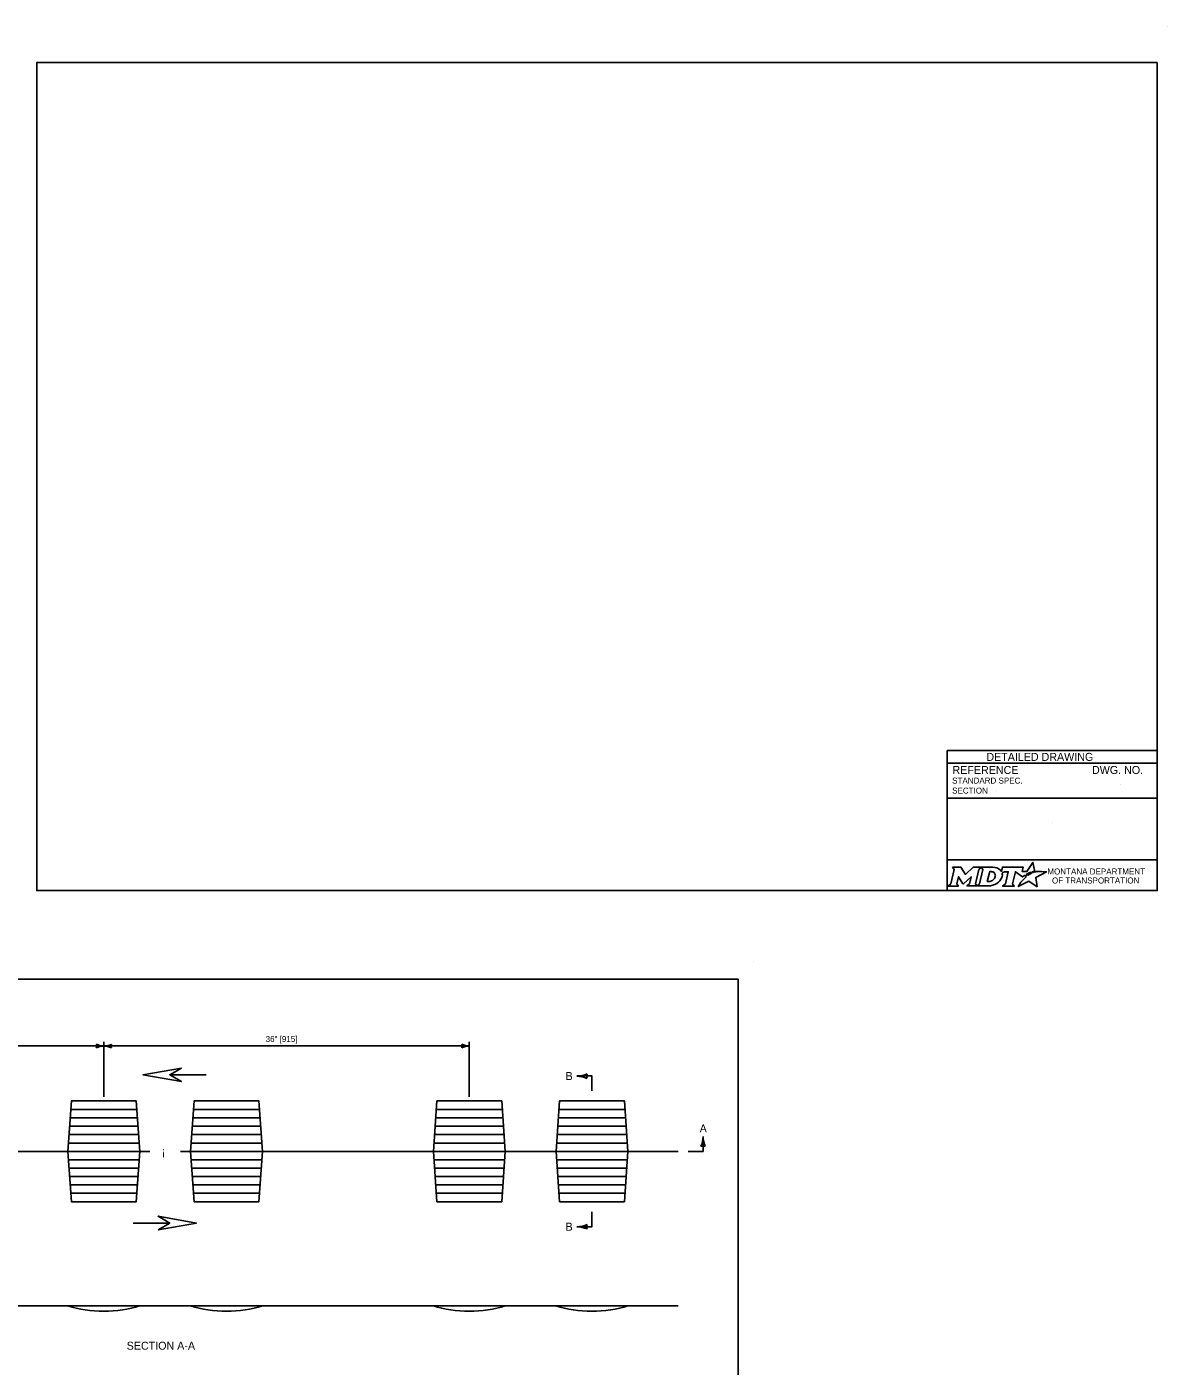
# Model space of a CAD drawing. Extents: x 49937 to 50080, y 49883 to 50108.
# Drawn here: x 50009.64 to 50021.04, y 49995.13 to 50008.52 of the extents above; entities that cross this region are included whole.
import ezdxf

# ---------------------------------------------------------------- set-up
doc = ezdxf.new("R2010")
doc.units = 0
for name, color, linetype in [('Default', 7, 'Continuous'), ('Level 1', 7, 'Continuous'), ('Level 2', 7, 'Continuous'), ('Level 3', 7, 'Continuous'), ('Level 4', 7, 'Continuous'), ('Level 5', 7, 'Continuous'), ('Level 6', 7, 'Continuous')]:
    doc.layers.add(name, color=color, linetype=linetype)

msp = doc.modelspace()

# ---------------------------------------------------------------- linework, layer by layer
at = {"layer": 'Default'}
for points in [[(50018.893, 50000.121), (50018.907, 50000.097), (50018.874, 49999.954), (50018.848, 49999.931), (50018.95, 49999.931), (50018.936, 49999.954), (50018.952, 50000.024), (50018.996, 49999.955), (50019.002, 49999.955), (50019.077, 50000.025), (50019.06, 49999.954), (50019.035, 49999.932), (50019.137, 49999.932), (50019.123, 49999.955), (50019.156, 50000.097)], [(50019.156, 50000.097), (50019.182, 50000.121), (50019.099, 50000.121), (50019.02, 50000.048), (50018.975, 50000.12), (50018.893, 50000.121)], [(50019.295, 50000.121), (50019.182, 50000.121), (50019.196, 50000.098), (50019.163, 49999.954), (50019.137, 49999.932), (50019.248, 49999.932)], [(50019.7, 50000.068), (50019.69, 50000.074), (50019.702, 50000.076), (50019.713, 50000.078), (50019.696, 50000.168), (50019.636, 50000.077), (50019.589, 50000.076), (50019.599, 50000.12), (50019.39, 50000.121), (50019.38, 50000.078), (50019.374, 50000.086)], [(50019.319, 50000.034), (50019.318, 50000.026), (50019.315, 50000.017), (50019.311, 50000.008), (50019.305, 50000.001), (50019.299, 49999.994), (50019.291, 49999.988), (50019.282, 49999.983), (50019.273, 49999.979), (50019.264, 49999.977), (50019.255, 49999.976), (50019.239, 49999.976), (50019.263, 50000.076), (50019.279, 50000.076), (50019.286, 50000.075), (50019.294, 50000.073), (50019.301, 50000.07), (50019.307, 50000.066), (50019.311, 50000.061), (50019.315, 50000.055), (50019.318, 50000.049), (50019.319, 50000.042), (50019.32, 50000.038), (50019.319, 50000.034)], [(50019.293, 49999.939), (50019.302, 49999.942), (50019.315, 49999.947), (50019.335, 49999.958)], [(50019.387, 50000.062), (50019.411, 50000.075), (50019.448, 50000.075), (50019.42, 49999.954), (50019.392, 49999.931), (50019.508, 49999.931), (50019.491, 49999.954), (50019.52, 50000.075), (50019.591, 50000.023), (50019.612, 50000.038), (50019.632, 50000.027)], [(50019.576, 49999.971), (50019.561, 49999.947), (50019.556, 49999.939), (50019.55, 49999.931), (50019.548, 49999.926), (50019.653, 49999.979), (50019.737, 49999.924), (50019.724, 50000.017), (50019.831, 50000.075), (50019.782, 50000.076), (50019.751, 50000.077), (50019.731, 50000.077), (50019.724, 50000.075), (50019.719, 50000.074), (50019.711, 50000.072), (50019.7, 50000.068)], [(50019.59, 49999.987), (50019.59, 49999.987)], [(50019.65, 50000.04), (50019.648, 50000.039), (50019.629, 50000.048), (50019.639, 50000.054), (50019.644, 50000.056), (50019.652, 50000.06), (50019.658, 50000.063), (50019.666, 50000.066), (50019.673, 50000.068), (50019.685, 50000.061), (50019.681, 50000.059), (50019.676, 50000.056), (50019.672, 50000.054), (50019.667, 50000.051), (50019.665, 50000.05), (50019.662, 50000.049), (50019.66, 50000.047), (50019.658, 50000.046), (50019.655, 50000.044), (50019.652, 50000.042), (50019.65, 50000.04)]]:
    msp.add_lwpolyline(points, dxfattribs=at)
for centre, radius, start, end in [((50019.274, 50000.059), 0.118, 300.9103, 339.1383), ((50019.319, 50000.042), 0.0709, 339.5329, 15.8582)]:
    msp.add_arc(centre, radius, start, end, dxfattribs=at)
for centre, major_axis, ratio, start_param, end_param in [((50019.293, 50000.073), (0.0834, -0.0037), 0.568097, 0.61298, 1.570796), ((50019.349, 50000.081), (0.0361, -0.0295), 0.469099, 1.225588, 1.570796), ((50019.583, 49999.979), (-0.00694, -0.00806), 0.008222, 0, 3.137361), ((50019.6, 49999.997), (-0.0098, -0.0102), 0.016458, 3.141593, 6.279097), ((50019.621, 50000.017), (-0.0112, -0.0097), 0.021651, 3.157348, 6.283185), ((50019.248, 50000.08), (0, 0.148), 0.987302, 3.139398, 3.456847)]:
    msp.add_ellipse(centre, major_axis=major_axis, ratio=ratio, start_param=start_param, end_param=end_param, dxfattribs=at)
at = {"layer": 'Level 1'}
for p, q in [((50021.038, 50008.524), (50021.038, 50008.524)), ((50016.9, 49999.176), (50016.9, 49999.176)), ((50011.432, 49998.044), (50011.066, 49998.044)), ((50011.432, 49998.043), (50011.066, 49998.043)), ((50010.077, 49997.698), (50010.737, 49997.698)), ((50011.303, 49997.698), (50011.964, 49997.698)), ((50013.731, 49997.698), (50014.391, 49997.698)), ((50014.957, 49997.698), (50015.617, 49997.698)), ((50010.071, 49997.614), (50010.743, 49997.614)), ((50011.298, 49997.614), (50011.969, 49997.614)), ((50013.725, 49997.614), (50014.397, 49997.614)), ((50014.951, 49997.614), (50015.623, 49997.614)), ((50010.06, 49997.446), (50010.755, 49997.446)), ((50010.065, 49997.53), (50010.749, 49997.53)), ((50011.286, 49997.446), (50011.981, 49997.446)), ((50011.292, 49997.53), (50011.975, 49997.53)), ((50013.713, 49997.446), (50014.409, 49997.446)), ((50013.719, 49997.53), (50014.403, 49997.53)), ((50014.94, 49997.446), (50015.635, 49997.446)), ((50014.946, 49997.53), (50015.629, 49997.53)), ((50010.054, 49997.362), (50010.761, 49997.362)), ((50011.28, 49997.362), (50011.987, 49997.362)), ((50013.708, 49997.362), (50014.415, 49997.362)), ((50014.934, 49997.362), (50015.641, 49997.362)), ((50010.054, 49997.194), (50010.761, 49997.194)), ((50011.28, 49997.194), (50011.987, 49997.194)), ((50013.708, 49997.194), (50014.415, 49997.194)), ((50014.934, 49997.194), (50015.641, 49997.194)), ((50010.06, 49997.11), (50010.755, 49997.11)), ((50010.065, 49997.026), (50010.749, 49997.026)), ((50011.286, 49997.11), (50011.981, 49997.11)), ((50011.292, 49997.026), (50011.975, 49997.026)), ((50013.713, 49997.11), (50014.409, 49997.11)), ((50013.719, 49997.026), (50014.403, 49997.026)), ((50014.94, 49997.11), (50015.635, 49997.11)), ((50014.946, 49997.026), (50015.629, 49997.026)), ((50010.071, 49996.943), (50010.743, 49996.943)), ((50011.298, 49996.943), (50011.969, 49996.943)), ((50013.725, 49996.943), (50014.397, 49996.943)), ((50014.951, 49996.943), (50015.623, 49996.943)), ((50010.077, 49996.859), (50010.737, 49996.859)), ((50011.303, 49996.859), (50011.964, 49996.859)), ((50013.731, 49996.859), (50014.391, 49996.859)), ((50014.957, 49996.859), (50015.617, 49996.859)), ((50010.702, 49996.561), (50011.067, 49996.561)), ((50010.702, 49996.561), (50011.067, 49996.561)), ((50005.894, 49995.734), (50016.148, 49995.734))]:
    msp.add_line(p, q, dxfattribs=at)
for points in [[(50020.938, 50008.165), (50009.737, 50008.165), (50009.737, 49999.886), (50020.938, 49999.886)], [(49999.384, 49998.999), (50016.75, 49998.999), (50016.75, 49987.799), (49999.384, 49987.799)], [(50011.183, 49998.111), (50010.799, 49998.044), (50011.183, 49997.976), (50011.066, 49998.044)], [(50010.048, 49997.278), (50010.083, 49997.782), (50010.732, 49997.782), (50010.767, 49997.278), (50010.732, 49996.775), (50010.083, 49996.775)], [(50011.274, 49997.278), (50011.309, 49997.782), (50011.958, 49997.782), (50011.993, 49997.278), (50011.958, 49996.775), (50011.309, 49996.775)], [(50013.702, 49997.278), (50013.737, 49997.782), (50014.385, 49997.782), (50014.42, 49997.278), (50014.385, 49996.775), (50013.737, 49996.775)], [(50014.928, 49997.278), (50014.963, 49997.782), (50015.612, 49997.782), (50015.647, 49997.278), (50015.612, 49996.775), (50014.963, 49996.775)], [(50010.95, 49996.493), (50011.333, 49996.561), (50010.95, 49996.629), (50011.067, 49996.561)]]:
    msp.add_lwpolyline(points, close=True, dxfattribs=at)
for centre in [(50010.407, 49996.013), (50011.634, 49996.013), (50014.061, 49996.013), (50015.287, 49996.013)]:
    msp.add_ellipse(centre, major_axis=(0.655, 0), ratio=0.509728, start_param=4.131771, end_param=5.293007, dxfattribs=at)
at = {"layer": 'Level 3'}
for p, q in [((50010.407, 49997.822), (50010.407, 49998.372)), ((50014.061, 49997.822), (50014.061, 49998.372)), ((50007.98, 49998.332), (50010.407, 49998.332)), ((50010.407, 49998.332), (50014.061, 49998.332))]:
    msp.add_line(p, q, dxfattribs=at)
for centre, radius, start, end in [((50010.416, 49998.554), 0.222, 247.4703, 267.6538), ((50010.279, 49998.331), 0.0548, 342.1531, 17.8755), ((50010.396, 49998.564), 0.233, 272.8416, 292.0915), ((50010.535, 49998.332), 0.0548, 162.1531, 197.8755), ((50014.07, 49998.554), 0.222, 247.4703, 267.6538), ((50013.933, 49998.331), 0.0548, 342.1531, 17.8755), ((50010.419, 49998.099), 0.233, 92.8416, 112.0915), ((50010.398, 49998.109), 0.222, 67.4703, 87.6538), ((50014.073, 49998.099), 0.233, 92.8416, 112.0915)]:
    msp.add_arc(centre, radius, start, end, dxfattribs=at)
at = {"layer": 'Level 4'}
for p, q in [((50020.938, 50001.286), (50018.838, 50001.286)), ((50018.838, 50001.286), (50018.838, 49999.886)), ((50020.938, 50001.161), (50018.838, 50001.161)), ((50020.574, 50000.946), (50020.574, 50000.946)), ((50020.938, 50000.811), (50018.838, 50000.811)), ((50019.332, 50000.886), (50019.332, 50000.886)), ((50019.888, 50000.562), (50019.888, 50000.562)), ((50020.938, 50000.193), (50018.838, 50000.193))]:
    msp.add_line(p, q, dxfattribs=at)
at = {"layer": 'Level 5'}
for p, q in [((50005.894, 49997.278), (50010.867, 49997.278)), ((50011.174, 49997.278), (50016.148, 49997.278))]:
    msp.add_line(p, q, dxfattribs=at)
at = {"layer": 'Level 6'}
for points in [[(50015.287, 49997.882), (50015.287, 49998.032), (50015.137, 49998.032)], [(50016.248, 49997.278), (50016.398, 49997.278), (50016.398, 49997.428)], [(50015.287, 49996.675), (50015.287, 49996.525), (50015.137, 49996.525)]]:
    msp.add_lwpolyline(points, dxfattribs=at)
for centre, radius, start, end in [((50015.122, 49998.342), 0.311, 272.8416, 292.0915), ((50015.125, 49997.735), 0.296, 67.4703, 87.6538), ((50015.308, 49998.032), 0.073, 162.1531, 197.8755), ((50016.102, 49997.44), 0.296, 337.4703, 357.6538), ((50016.708, 49997.444), 0.311, 182.8416, 202.0915), ((50016.398, 49997.257), 0.073, 72.1531, 107.8755), ((50015.122, 49996.835), 0.311, 272.8416, 292.0915), ((50015.125, 49996.229), 0.296, 67.4703, 87.6538), ((50015.308, 49996.525), 0.073, 162.1531, 197.8755)]:
    msp.add_arc(centre, radius, start, end, dxfattribs=at)

# ---------------------------------------------------------------- texts
at = {"layer": 'Default'}
for s, p in [('MONTANA DEPARTMENT', (50019.84, 50000.047)), ('OF TRANSPORTATION', (50019.886, 49999.957))]:
    msp.add_text(s, height=0.06, rotation=360, dxfattribs=at).set_placement(p)
at = {"layer": 'Level 2'}
for s, height, p in [('36" [915]', 0.06, (50012.025, 49998.372)), ('B', 0.08, (50015.023, 49997.992)), ('A', 0.08, (50016.364, 49997.468)), ('¡', 0.08, (50010.987, 49997.238)), ('B', 0.08, (50015.023, 49996.485)), ('SECTION A-A', 0.08, (50010.636, 49995.295))]:
    msp.add_text(s, height=height, dxfattribs=at).set_placement(p)
at = {"layer": 'Level 4'}
for s, height, p in [('DETAILED DRAWING', 0.0799, (50019.23, 50001.183)), ('REFERENCE', 0.08, (50018.891, 50001.052)), ('DWG. NO.', 0.08, (50020.286, 50001.052)), ('STANDARD SPEC.', 0.06, (50018.888, 50000.956)), ('SECTION', 0.06, (50018.888, 50000.856))]:
    msp.add_text(s, height=height, dxfattribs=at).set_placement(p)

doc.saveas('drawing.dxf')
